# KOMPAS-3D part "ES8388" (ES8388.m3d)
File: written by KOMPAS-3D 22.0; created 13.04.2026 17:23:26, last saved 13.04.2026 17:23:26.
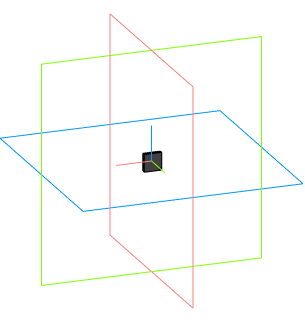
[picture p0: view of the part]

Document properties: Автор: Andrey; Полное имя файла: C:\Users\User1\Documents\ES8388.m3d

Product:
- Part/product: ES8388

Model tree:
1. Операция без истории:1
2. Операция без истории:2
3. Операция без истории:3
4. Операция без истории:4
5. Операция без истории:5
6. Операция без истории:6
7. Операция без истории:7
8. Операция без истории:8
9. Операция без истории:9
10. Операция без истории:10
11. Операция без истории:11
12. Операция без истории:12
13. Операция без истории:13
14. Операция без истории:14
15. Операция без истории:15
16. Операция без истории:16
17. Операция без истории:17
18. Операция без истории:18
19. Операция без истории:19
20. Операция без истории:20
21. Операция без истории:21
22. Операция без истории:22
23. Операция без истории:23
24. Операция без истории:24
25. Операция без истории:25
26. Операция без истории:26
27. Операция без истории:27
28. Операция без истории:28
29. Операция без истории:29
30. Операция без истории:30
31. Операция без истории:31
